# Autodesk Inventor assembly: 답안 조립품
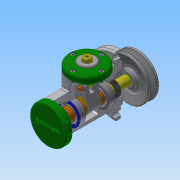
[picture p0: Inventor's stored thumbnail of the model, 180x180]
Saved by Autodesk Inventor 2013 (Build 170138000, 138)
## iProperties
Created: 2016-08
Part Number: 답안 조립품
Document SubType Name: Assembly
Designer: Administrator
Author: Administrator
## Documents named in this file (25)
- C:\Users\Administrator\Favorites\Desktop\460808V1012\답안 조립품.iam
- C:\Users\Administrator\Favorites\Desktop\460808V1012\V-벨트풀리.ipt
- C:\Users\Administrator\Favorites\Desktop\460808V1012\너트 M10.ipt
- C:\Users\Administrator\Favorites\Desktop\460808V1012\링크.ipt
- C:\Users\Administrator\Favorites\Desktop\460808V1012\멈춤링 15 x 1.ipt
- C:\Users\Administrator\Favorites\Desktop\460808V1012\멈춤링 35x1.6.ipt
- C:\Users\Administrator\Favorites\Desktop\460808V1012\베어링 15 x 35 x 11.ipt
- C:\Users\Administrator\Favorites\Desktop\460808V1012\본체.ipt
- C:\Users\Administrator\Favorites\Desktop\460808V1012\볼트 M4 x 10.ipt
- C:\Users\Administrator\Favorites\Desktop\460808V1012\볼트 M4 x 12.ipt
- C:\Users\Administrator\Favorites\Desktop\460808V1012\부시1.ipt
- C:\Users\Administrator\Favorites\Desktop\460808V1012\부시2.ipt
- C:\Users\Administrator\Favorites\Desktop\460808V1012\분할핀 1.6 x 12.ipt
- C:\Users\Administrator\Favorites\Desktop\460808V1012\사이드 커버.ipt
- 사이드 커버.ipt
- C:\Users\Administrator\Favorites\Desktop\460808V1012\슬라이더.ipt
- C:\Users\Administrator\Favorites\Desktop\460808V1012\오일 실 15 25 7.ipt
- C:\Users\Administrator\Favorites\Desktop\460808V1012\와셔 4x16.ipt
- C:\Users\Administrator\Favorites\Desktop\460808V1012\와셔 10x21.ipt
- C:\Users\Administrator\Favorites\Desktop\460808V1012\클래스터 핀 6 x 24.ipt
- C:\Users\Administrator\Favorites\Desktop\460808V1012\키 4 x 4 x 18.ipt
- C:\Users\Administrator\Favorites\Desktop\460808V1012\탑 부시.ipt
- C:\Users\Administrator\Favorites\Desktop\460808V1012\탑 커버.ipt
- 탑 커버.ipt
- C:\Users\Administrator\Favorites\Desktop\460808V1012\편심축.ipt
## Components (6 placed, 3 different names)
1. V-벨트풀리:1 — 각도:8
2. ISO 4017 M4 x 10:1
3. ISO 4762 M4 x 12:1
4. ISO 4762 M4 x 12:2
5. ISO 4762 M4 x 12:3
6. ISO 4762 M4 x 12:4
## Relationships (1: Angle 1)
- 각도:8 [Angle]: V-벨트풀리:1
